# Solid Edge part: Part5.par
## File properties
Author: Deepak Maini
Template: Normal.par
Last saved by: MYPC
Revision: 2
Application: Solid Edge
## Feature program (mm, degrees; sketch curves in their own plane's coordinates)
body "unnamed Body 1"
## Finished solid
Body 1: solid body, 82 faces, 169 edges, 90 vertices.
  Faces by surface: cylinder 44, plane 27, torus 6, spline 3, cone 2
  Edges by curve: circle 64, ellipse 44, line 26, intersection 24, curve on surface 11
Bounding box of the edges (mm; curved faces can reach further): 3403.600 x 1854.200 x 1930.410, from (-1701.8, 0, -965.2014) to (1701.8, 1854.2, 965.2088).
Cylindrical faces by radius (mm): R63.5 x26, R76.2 x4, R95.25 x4, R317.5 x4, R342.9 x3, R558.8 x1, R965.2 x2
Conical faces (half-angle, radius in mm at the cone's reference point): 15 deg R654.5026 x1, 16.46 deg R711.4955 x1
Toroidal faces (ring radius, tube radius in mm): R408.1559 r101.6 x1, R609.6 r50.8 x1, R851.7802 r50.8 x1, R889 r76.2 x2, R983.9044 r127 x1
Planar faces by outward normal: +y 20, +z 1, -y 5, -z 1
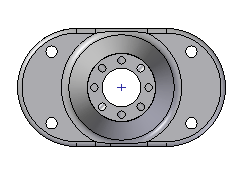
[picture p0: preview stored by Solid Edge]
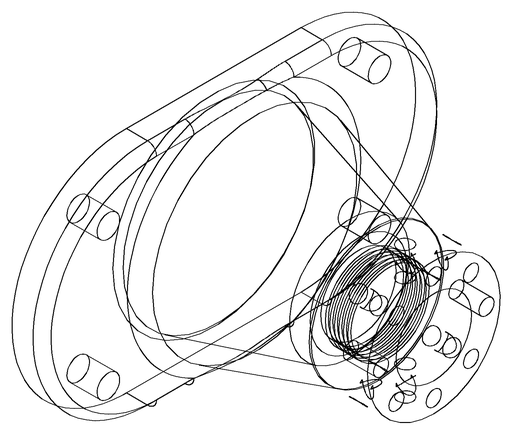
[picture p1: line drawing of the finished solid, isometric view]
